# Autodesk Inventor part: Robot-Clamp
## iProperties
Shininess: 21.0
Length Units: 11269
Angle Units: 11279
Time Units: 11290
Mass Units: 11283
Length Display Precision: 3
Angle Display Precision: 2
Created: 2001-08
Part Number: Robot-Clamp
Document SubType Name: ﾓﾃﾞﾘﾝｸﾞ
Designer: Administrator
Density: 1 g/cm^3
Density: 0.0
Volumn: 0.0
Area: 0.0
PropertySet Name: Model Information
Control State: 0
Master: False
Checked Out: False
Author: Administrator
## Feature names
1. Extrusion1
